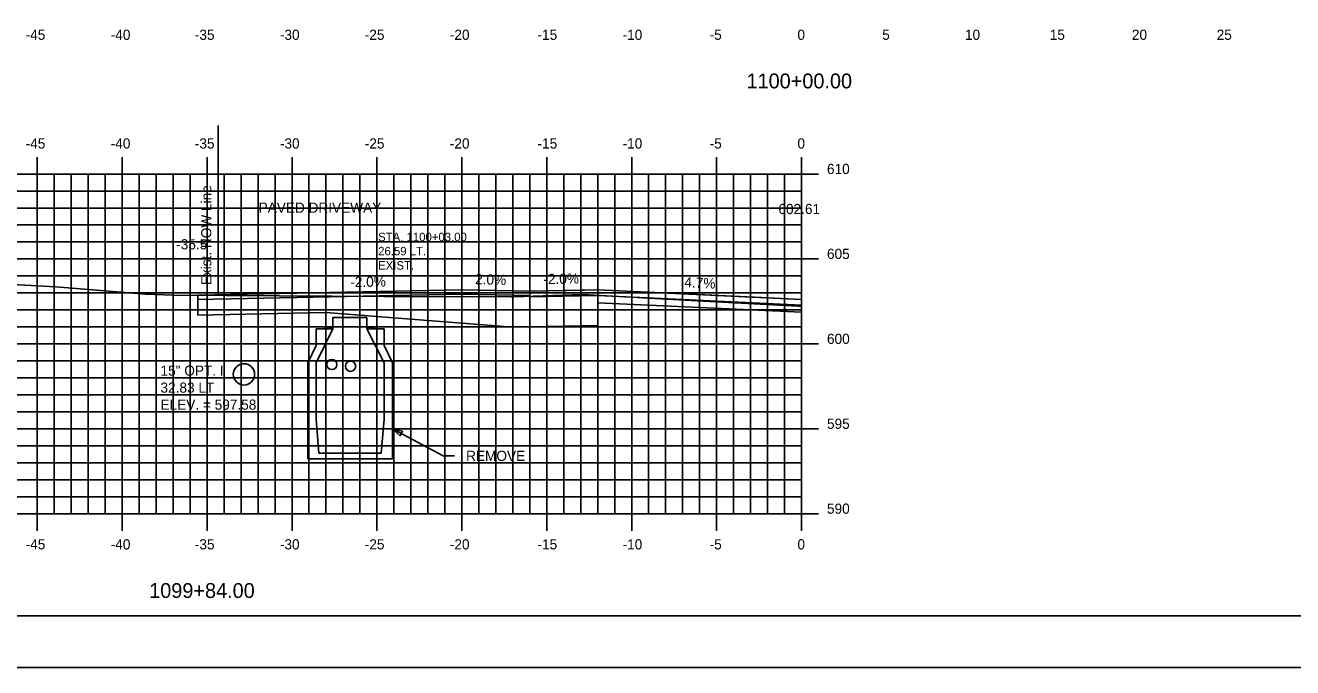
# Model space of a CAD drawing. Extents: x 1076304 to 1076474, y 779716 to 779826.
# Drawn here: x 1076341.1 to 1076415.7, y 779715.6 to 779753.5 of the extents above; entities that cross this region are included whole.
import ezdxf

# ---------------------------------------------------------------- set-up
doc = ezdxf.new("R2010")
doc.units = 0
for name, color, linetype in [('ANNOTATION', 7, 'Continuous'), ('BORDER', 7, 'Continuous'), ('D_Drainage_Culvert', 7, 'Continuous'), ('D_Roadway_Centerline', 7, 'Continuous'), ('D_Roadway_Centerline_Text', 7, 'Continuous'), ('D_Roadway_Drive_Paved', 7, 'Continuous'), ('D_Roadway_Drive_SubGrade', 7, 'Continuous'), ('D_Roadway_Edge_Pavement', 7, 'Continuous'), ('D_Roadway_Edge_Shoulder', 7, 'Continuous'), ('D_Roadway_Pavement', 7, 'Continuous'), ('D_Roadway_SubGrade', 7, 'Continuous'), ('D_Text_Monospaced', 7, 'Continuous'), ('D_Text_Standard', 7, 'Continuous'), ('E_ROW_Line', 7, 'Continuous'), ('H_V ANNOTATION', 7, 'Continuous'), ('MAJOR', 7, 'Continuous'), ('MINOR', 7, 'Continuous'), ('PLOT BOUNDARY', 7, 'Continuous'), ('S_Drainage_CB', 7, 'Continuous'), ('S_Drainage_Invert', 7, 'Continuous'), ('S_Roadway_Centerline', 7, 'Continuous')]:
    doc.layers.add(name, color=color, linetype=linetype)

msp = doc.modelspace()

# ---------------------------------------------------------------- linework, layer by layer
at = {"layer": 'BORDER'}
msp.add_lwpolyline([(1076311.794, 779718.706), (1076471.794, 779718.706), (1076471.794, 779823.706), (1076311.794, 779823.706)], close=True, dxfattribs=at)
at = {"layer": 'D_Drainage_Culvert'}
msp.add_circle((1076353.964, 779732.911), 0.625, dxfattribs=at)
at = {"layer": 'D_Roadway_Centerline'}
msp.add_lwpolyline([(1076370.797, 779737.801), (1076370.797, 779737.801), (1076374.011, 779737.866), (1076374.797, 779737.881), (1076384.448, 779737.428), (1076386.794, 779737.317)], dxfattribs=at)
at = {"layer": 'D_Roadway_Drive_Paved'}
for points in [[(1076370.797, 779737.801), (1076366.794, 779737.881), (1076351.252, 779737.57)], [(1076370.794, 779737.551), (1076366.794, 779737.631), (1076351.252, 779737.32)]]:
    msp.add_lwpolyline(points, dxfattribs=at)
at = {"layer": 'D_Roadway_Drive_SubGrade'}
msp.add_lwpolyline([(1076370.794, 779735.718), (1076369.794, 779735.698), (1076358.794, 779736.554), (1076351.252, 779736.404), (1076351.252, 779737.57)], dxfattribs=at)
at = {"layer": 'D_Roadway_Edge_Pavement'}
for p, q in [((1076374.794, 779737.548), (1076386.794, 779736.984)), ((1076374.797, 779737.881), (1076386.794, 779737.317))]:
    msp.add_line(p, q, dxfattribs=at)
at = {"layer": 'D_Roadway_Edge_Shoulder'}
msp.add_lwpolyline([(1076374.797, 779737.881), (1076370.797, 779737.801), (1076370.797, 779737.468), (1076374.797, 779737.548)], close=True, dxfattribs=at)
at = {"layer": 'D_Roadway_Pavement'}
msp.add_line((1076374.794, 779737.131), (1076386.794, 779736.567), dxfattribs=at)
msp.add_lwpolyline([(1076374.797, 779737.548), (1076374.797, 779737.131)], dxfattribs=at)
at = {"layer": 'D_Roadway_SubGrade'}
msp.add_lwpolyline([(1076374.797, 779737.548), (1076370.797, 779737.468), (1076370.797, 779737.801), (1076370.794, 779735.718), (1076374.797, 779735.798), (1076374.797, 779737.548)], close=True, dxfattribs=at)
at = {"layer": 'D_Text_Standard'}
msp.add_lwpolyline([(1076362.709, 779729.706), (1076365.685, 779728.117), (1076366.365, 779728.117)], dxfattribs=at)
msp.add_lwpolyline([(1076362.709, 779729.706), (1076363.291, 779729.56), (1076363.154, 779729.303)], close=True, dxfattribs=at)
at = {"layer": 'E_ROW_Line'}
msp.add_line((1076352.446, 779737.562), (1076352.446, 779747.562), dxfattribs=at)
msp.add_line((1076352.446, 779737.562), (1076352.446, 779747.562), dxfattribs=at)
at = {"layer": 'MAJOR'}
for p, q in [((1076341.794, 779745.708), (1076341.794, 779744.706)), ((1076346.794, 779745.708), (1076346.794, 779744.706)), ((1076351.794, 779745.708), (1076351.794, 779744.706)), ((1076356.794, 779745.708), (1076356.794, 779744.706)), ((1076361.794, 779745.708), (1076361.794, 779744.706)), ((1076366.794, 779745.708), (1076366.794, 779744.706)), ((1076371.794, 779745.708), (1076371.794, 779744.706)), ((1076376.794, 779745.708), (1076376.794, 779744.706)), ((1076381.794, 779745.708), (1076381.794, 779744.706)), ((1076386.794, 779745.708), (1076386.794, 779744.706)), ((1076316.794, 779744.706), (1076386.794, 779744.706)), ((1076316.794, 779744.706), (1076386.794, 779744.706)), ((1076341.794, 779724.706), (1076341.794, 779744.706)), ((1076346.794, 779724.706), (1076346.794, 779744.706)), ((1076351.794, 779724.706), (1076351.794, 779744.706)), ((1076356.794, 779724.706), (1076356.794, 779744.706)), ((1076361.794, 779724.706), (1076361.794, 779744.706)), ((1076366.794, 779724.706), (1076366.794, 779744.706)), ((1076371.794, 779724.706), (1076371.794, 779744.706)), ((1076376.794, 779724.706), (1076376.794, 779744.706)), ((1076381.794, 779724.706), (1076381.794, 779744.706)), ((1076387.796, 779744.706), (1076385.792, 779744.706)), ((1076386.794, 779724.706), (1076386.794, 779744.706)), ((1076386.794, 779724.706), (1076386.794, 779744.706)), ((1076316.794, 779739.706), (1076386.794, 779739.706)), ((1076387.796, 779739.706), (1076385.792, 779739.706)), ((1076316.794, 779734.706), (1076386.794, 779734.706)), ((1076387.796, 779734.706), (1076385.792, 779734.706)), ((1076316.794, 779729.706), (1076386.794, 779729.706)), ((1076387.796, 779729.706), (1076385.792, 779729.706)), ((1076316.794, 779724.706), (1076386.794, 779724.706)), ((1076316.794, 779724.706), (1076386.794, 779724.706)), ((1076341.794, 779723.704), (1076341.794, 779724.706)), ((1076346.794, 779723.704), (1076346.794, 779724.706)), ((1076351.794, 779723.704), (1076351.794, 779724.706)), ((1076356.794, 779723.704), (1076356.794, 779724.706)), ((1076361.794, 779723.704), (1076361.794, 779724.706)), ((1076366.794, 779723.704), (1076366.794, 779724.706)), ((1076371.794, 779723.704), (1076371.794, 779724.706)), ((1076376.794, 779723.704), (1076376.794, 779724.706)), ((1076381.794, 779723.704), (1076381.794, 779724.706)), ((1076387.796, 779724.706), (1076385.792, 779724.706)), ((1076386.794, 779723.704), (1076386.794, 779724.706))]:
    msp.add_line(p, q, dxfattribs=at)
at = {"layer": 'MINOR'}
for p, q in [((1076342.794, 779724.706), (1076342.794, 779744.706)), ((1076343.794, 779724.706), (1076343.794, 779744.706)), ((1076344.794, 779724.706), (1076344.794, 779744.706)), ((1076345.794, 779724.706), (1076345.794, 779744.706)), ((1076347.794, 779724.706), (1076347.794, 779744.706)), ((1076348.794, 779724.706), (1076348.794, 779744.706)), ((1076349.794, 779724.706), (1076349.794, 779744.706)), ((1076350.794, 779724.706), (1076350.794, 779744.706)), ((1076352.794, 779724.706), (1076352.794, 779744.706)), ((1076353.794, 779724.706), (1076353.794, 779744.706)), ((1076354.794, 779724.706), (1076354.794, 779744.706)), ((1076355.794, 779724.706), (1076355.794, 779744.706)), ((1076357.794, 779724.706), (1076357.794, 779744.706)), ((1076358.794, 779724.706), (1076358.794, 779744.706)), ((1076359.794, 779724.706), (1076359.794, 779744.706)), ((1076360.794, 779724.706), (1076360.794, 779744.706)), ((1076362.794, 779724.706), (1076362.794, 779744.706)), ((1076363.794, 779724.706), (1076363.794, 779744.706)), ((1076364.794, 779724.706), (1076364.794, 779744.706)), ((1076365.794, 779724.706), (1076365.794, 779744.706)), ((1076367.794, 779724.706), (1076367.794, 779744.706)), ((1076368.794, 779724.706), (1076368.794, 779744.706)), ((1076369.794, 779724.706), (1076369.794, 779744.706)), ((1076370.794, 779724.706), (1076370.794, 779744.706)), ((1076372.794, 779724.706), (1076372.794, 779744.706)), ((1076373.794, 779724.706), (1076373.794, 779744.706)), ((1076374.794, 779724.706), (1076374.794, 779744.706)), ((1076375.794, 779724.706), (1076375.794, 779744.706)), ((1076377.794, 779724.706), (1076377.794, 779744.706)), ((1076378.794, 779724.706), (1076378.794, 779744.706)), ((1076379.794, 779724.706), (1076379.794, 779744.706)), ((1076380.794, 779724.706), (1076380.794, 779744.706)), ((1076382.794, 779724.706), (1076382.794, 779744.706)), ((1076383.794, 779724.706), (1076383.794, 779744.706)), ((1076384.794, 779724.706), (1076384.794, 779744.706)), ((1076385.794, 779724.706), (1076385.794, 779744.706)), ((1076316.794, 779743.706), (1076386.794, 779743.706)), ((1076386.794, 779743.706), (1076385.792, 779743.706)), ((1076316.794, 779742.706), (1076386.794, 779742.706)), ((1076386.794, 779742.706), (1076385.792, 779742.706)), ((1076316.794, 779741.706), (1076386.794, 779741.706)), ((1076386.794, 779741.706), (1076385.792, 779741.706)), ((1076316.794, 779740.706), (1076386.794, 779740.706)), ((1076386.794, 779740.706), (1076385.792, 779740.706)), ((1076316.794, 779738.706), (1076386.794, 779738.706)), ((1076386.794, 779738.706), (1076385.792, 779738.706)), ((1076316.794, 779737.706), (1076386.794, 779737.706)), ((1076386.794, 779737.706), (1076385.792, 779737.706)), ((1076316.794, 779736.706), (1076386.794, 779736.706)), ((1076386.794, 779736.706), (1076385.792, 779736.706)), ((1076316.794, 779735.706), (1076386.794, 779735.706)), ((1076386.794, 779735.706), (1076385.792, 779735.706)), ((1076316.794, 779733.706), (1076386.794, 779733.706)), ((1076386.794, 779733.706), (1076385.792, 779733.706)), ((1076316.794, 779732.706), (1076386.794, 779732.706)), ((1076386.794, 779732.706), (1076385.792, 779732.706)), ((1076316.794, 779731.706), (1076386.794, 779731.706)), ((1076386.794, 779731.706), (1076385.792, 779731.706)), ((1076316.794, 779730.706), (1076386.794, 779730.706)), ((1076386.794, 779730.706), (1076385.792, 779730.706)), ((1076316.794, 779728.706), (1076386.794, 779728.706)), ((1076386.794, 779728.706), (1076385.792, 779728.706)), ((1076316.794, 779727.706), (1076386.794, 779727.706)), ((1076386.794, 779727.706), (1076385.792, 779727.706)), ((1076316.794, 779726.706), (1076386.794, 779726.706)), ((1076386.794, 779726.706), (1076385.792, 779726.706)), ((1076316.794, 779725.706), (1076386.794, 779725.706)), ((1076386.794, 779725.706), (1076385.792, 779725.706))]:
    msp.add_line(p, q, dxfattribs=at)
at = {"layer": 'PLOT BOUNDARY'}
msp.add_lwpolyline([(1076303.701, 779715.646), (1076473.701, 779715.646), (1076473.701, 779825.646), (1076303.701, 779825.646)], close=True, dxfattribs=at)
at = {"layer": 'S_Drainage_CB'}
for p, q in [((1076359.199, 779735.589), (1076358.215, 779735.589)), ((1076358.215, 779735.589), (1076358.215, 779734.604)), ((1076358.215, 779733.587), (1076359.199, 779735.589)), ((1076362.217, 779735.589), (1076361.2, 779735.589)), ((1076361.2, 779735.589), (1076362.217, 779733.587)), ((1076362.217, 779734.604), (1076362.217, 779735.589)), ((1076358.215, 779734.604), (1076357.723, 779733.587)), ((1076362.709, 779733.587), (1076362.217, 779734.604)), ((1076357.723, 779733.587), (1076357.723, 779727.944)), ((1076358.215, 779730.274), (1076358.215, 779733.587)), ((1076362.217, 779733.587), (1076362.217, 779730.274)), ((1076362.709, 779727.944), (1076362.709, 779733.587)), ((1076358.379, 779728.272), (1076358.215, 779730.274)), ((1076362.217, 779730.274), (1076362.053, 779728.272)), ((1076357.723, 779727.944), (1076362.709, 779727.944)), ((1076362.053, 779728.272), (1076358.379, 779728.272))]:
    msp.add_line(p, q, dxfattribs=at)
msp.add_lwpolyline([(1076361.692, 779735.63), (1076361.2, 779735.63), (1076361.2, 779736.254), (1076359.199, 779736.254), (1076359.199, 779735.63), (1076358.707, 779735.63)], dxfattribs=at)
at = {"layer": 'S_Drainage_Invert'}
for centre in [(1076359.141, 779733.492), (1076360.244, 779733.39)]:
    msp.add_circle(centre, 0.3, dxfattribs=at)
at = {"layer": 'S_Roadway_Centerline'}
msp.add_lwpolyline([(1076316.794, 779738.515), (1076331.644, 779738.2), (1076338.118, 779738.318), (1076342.889, 779738.058), (1076348.166, 779737.635), (1076349.839, 779737.58), (1076365.336, 779737.471), (1076366.863, 779737.5), (1076369.684, 779737.485), (1076369.833, 779737.476), (1076373.897, 779737.618), (1076380.646, 779737.241), (1076386.578, 779736.927), (1076386.794, 779736.901)], dxfattribs=at)

# ---------------------------------------------------------------- texts
at = {"layer": 'ANNOTATION'}
for s, rotation, p in [('-2.0%', 1.14577, (1076360.232, 779738.045)), ('2.0%', 358.22308, (1076367.567, 779738.225)), ('-2.0%', 1.14577, (1076371.6, 779738.218)), ('4.7%', 357.30907, (1076379.886, 779738.043))]:
    msp.add_text(s, height=0.6, rotation=rotation, dxfattribs=at).set_placement(p)
for s, p in [('15" OPT. I', (1076349.051, 779732.834)), ('32.83 LT', (1076349.051, 779731.832)), ('ELEV. = 597.58', (1076349.051, 779730.83))]:
    msp.add_text(s, height=0.6, dxfattribs=at).set_placement(p)
at = {"layer": 'D_Roadway_Centerline_Text'}
msp.add_text('602.61', height=0.6, dxfattribs=at).set_placement((1076385.435, 779742.349))
at = {"layer": 'D_Text_Monospaced'}
for s, height, p in [('STA. 1100+03.00', 0.49998, (1076361.866, 779740.752)), ('26.59 LT.', 0.5, (1076361.866, 779739.918)), ('EXIST. ', 0.5, (1076361.866, 779739.078))]:
    msp.add_text(s, height=height, dxfattribs=at).set_placement(p)
at = {"layer": 'D_Text_Standard'}
for s, p in [('PAVED DRIVEWAY', (1076354.828, 779742.426)), ("-35.5'", (1076349.976, 779740.27)), ('REMOVE', (1076367.045, 779727.817))]:
    msp.add_text(s, height=0.6, dxfattribs=at).set_placement(p)
at = {"layer": 'E_ROW_Line'}
msp.add_text('Exist. ROW Line', height=0.6, rotation=90, dxfattribs=at).set_placement((1076352.046, 779738.162))
at = {"layer": 'H_V ANNOTATION'}
for s, height, p in [('-45', 0.6, (1076341.112, 779752.606)), ('-40', 0.6, (1076346.12, 779752.606)), ('-35', 0.6, (1076351.074, 779752.606)), ('-30', 0.6, (1076356.082, 779752.606)), ('-25', 0.6, (1076361.08, 779752.606)), ('-20', 0.6, (1076366.088, 779752.606)), ('-15', 0.6, (1076371.251, 779752.606)), ('-10', 0.6, (1076376.259, 779752.606)), ('-5', 0.6, (1076381.385, 779752.606)), ('0', 0.6, (1076386.553, 779752.606)), ('5', 0.6, (1076391.545, 779752.606)), ('10', 0.6, (1076396.42, 779752.606)), ('15', 0.6, (1076401.412, 779752.606)), ('20', 0.6, (1076406.248, 779752.606)), ('25', 0.6, (1076411.24, 779752.606)), ('1100+00.00', 0.875, (1076383.556, 779749.749)), ('-45', 0.6, (1076341.112, 779746.206)), ('-40', 0.6, (1076346.12, 779746.206)), ('-35', 0.6, (1076351.074, 779746.206)), ('-30', 0.6, (1076356.082, 779746.206)), ('-25', 0.6, (1076361.08, 779746.206)), ('-20', 0.6, (1076366.088, 779746.206)), ('-15', 0.6, (1076371.251, 779746.206)), ('-10', 0.6, (1076376.259, 779746.206)), ('-5', 0.6, (1076381.385, 779746.206)), ('0', 0.6, (1076386.553, 779746.206)), ('610', 0.6, (1076388.294, 779744.706)), ('605', 0.6, (1076388.294, 779739.706)), ('600', 0.6, (1076388.294, 779734.706)), ('595', 0.6, (1076388.294, 779729.706)), ('590', 0.6, (1076388.294, 779724.706)), ('-45', 0.6, (1076341.112, 779722.606)), ('-40', 0.6, (1076346.12, 779722.606)), ('-35', 0.6, (1076351.074, 779722.606)), ('-30', 0.6, (1076356.082, 779722.606)), ('-25', 0.6, (1076361.08, 779722.606)), ('-20', 0.6, (1076366.088, 779722.606)), ('-15', 0.6, (1076371.251, 779722.606)), ('-10', 0.6, (1076376.259, 779722.606)), ('-5', 0.6, (1076381.385, 779722.606)), ('0', 0.6, (1076386.553, 779722.606)), ('1099+84.00', 0.875, (1076348.385, 779719.749))]:
    msp.add_text(s, height=height, dxfattribs=at).set_placement(p)

doc.saveas('drawing.dxf')
